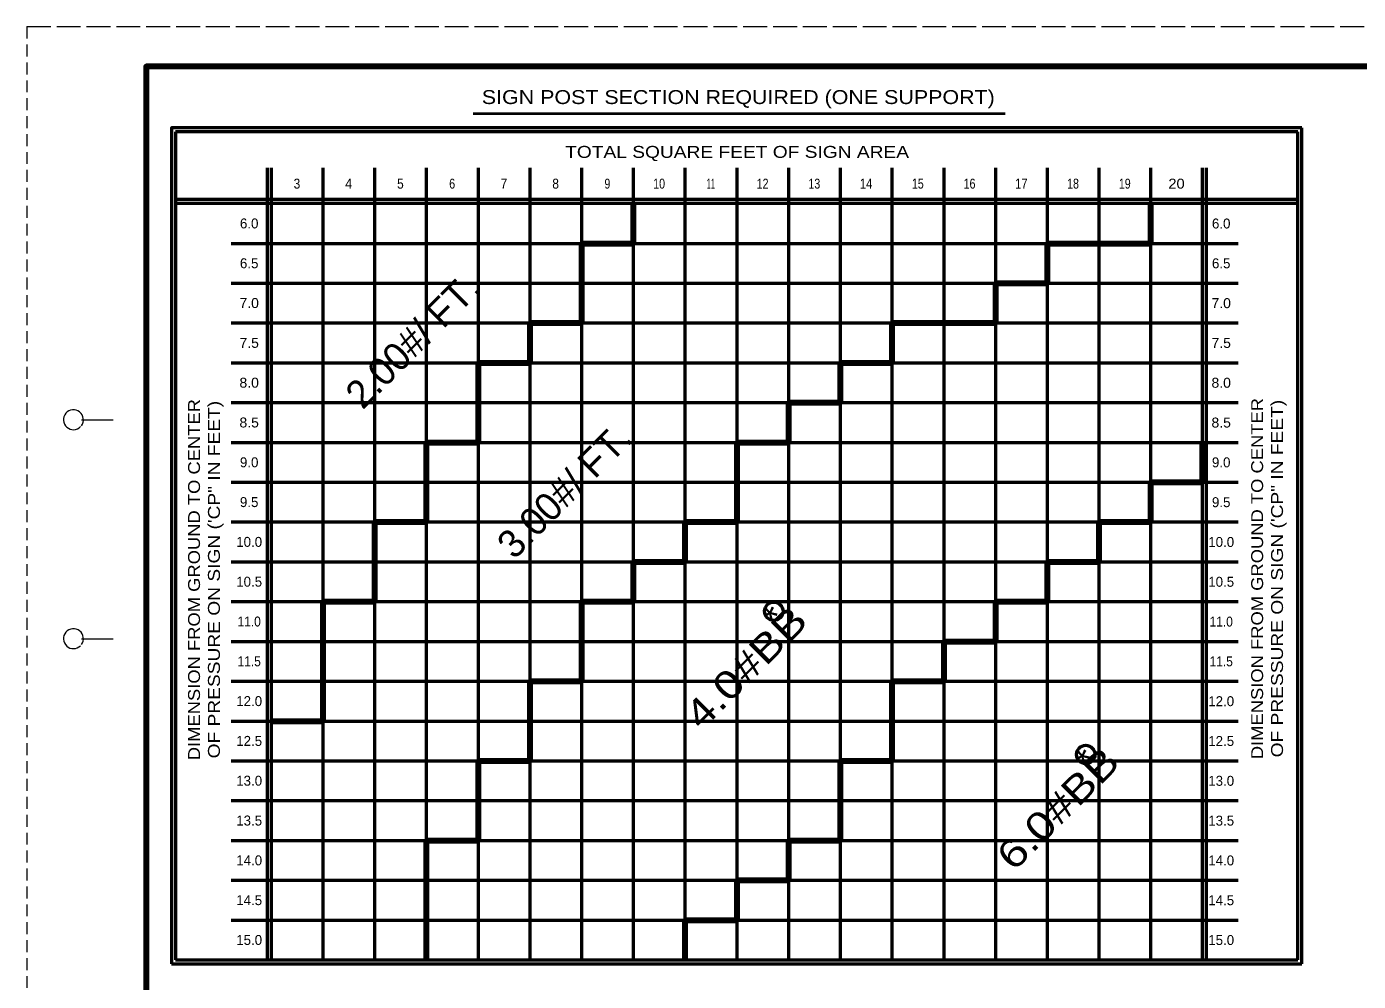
# Model space of a CAD drawing. Extents: x -2 to 678, y -1 to 439.
# Drawn here: x -1.8 to 332.9, y 199.5 to 439.3 of the extents above; entities that cross this region are included whole.
import ezdxf
from ezdxf.enums import TextEntityAlignment as Align

# ---------------------------------------------------------------- set-up
doc = ezdxf.new("R2010")
doc.units = 0
doc.linetypes.add('LONG_DASHED', pattern=[7.5, 6, -1.5])
doc.linetypes.add('MEDIUM_DASHED', pattern=[4.5, 3, -1.5])
doc.layers.add('1', color=7, linetype='Continuous', lineweight=53)
doc.layers.add('61', color=7, linetype='Continuous', lineweight=35)

msp = doc.modelspace()

# ---------------------------------------------------------------- linework, layer by layer
at = {"layer": '1', "linetype": 'MEDIUM_DASHED', "lineweight": 13}
msp.add_line((-1.693, 439.301), (-1.753, -0.739), dxfattribs=at)
at = {"layer": '1', "lineweight": 40}
msp.add_line((110.465, 417.498), (244.067, 417.498), dxfattribs=at)
at = {"layer": '1'}
for p, q in [((35.661, 412.86), (35.661, 204.86)), ((317.661, 412.86), (35.661, 412.86)), ((317.661, 204.86), (317.661, 412.86)), ((318.661, 203.86), (318.661, 413.86)), ((58.661, 403.86), (58.661, 204.86)), ((59.661, 403.86), (59.661, 204.86)), ((72.661, 403.86), (72.661, 395.86)), ((85.661, 403.86), (85.661, 314.86)), ((98.661, 403.86), (98.661, 334.86)), ((111.661, 403.86), (111.661, 354.86)), ((124.661, 403.86), (124.661, 364.86)), ((137.661, 403.86), (137.661, 384.86)), ((150.661, 403.86), (150.661, 394.86)), ((163.661, 403.86), (163.661, 314.86)), ((176.661, 403.86), (176.661, 334.86)), ((189.661, 403.86), (189.661, 344.86)), ((202.661, 403.86), (202.661, 354.86)), ((215.661, 403.86), (215.661, 364.86)), ((228.661, 403.86), (228.661, 284.86)), ((241.661, 403.86), (241.661, 374.86)), ((254.661, 403.86), (254.661, 384.86)), ((267.661, 403.86), (267.661, 314.86)), ((280.661, 403.86), (280.661, 394.86)), ((293.661, 334.86), (293.661, 403.86)), ((294.661, 204.86), (294.661, 403.86)), ((317.661, 395.86), (35.661, 395.86)), ((317.661, 394.86), (35.661, 394.86)), ((72.661, 395.86), (72.661, 294.86)), ((49.661, 384.86), (58.661, 384.86)), ((58.661, 384.86), (137.661, 384.86)), ((150.661, 384.86), (254.661, 384.86)), ((150.661, 384.86), (150.661, 304.86)), ((280.661, 384.86), (302.661, 384.86)), ((280.661, 384.86), (280.661, 324.86)), ((49.661, 374.86), (241.661, 374.86)), ((254.661, 374.86), (302.661, 374.86)), ((254.661, 374.86), (254.661, 304.86)), ((49.661, 364.86), (124.661, 364.86)), ((137.661, 364.86), (215.661, 364.86)), ((137.661, 364.86), (137.661, 294.86)), ((241.661, 364.86), (302.661, 364.86)), ((241.661, 364.86), (241.661, 294.86)), ((49.661, 354.86), (111.661, 354.86)), ((124.661, 354.86), (202.661, 354.86)), ((124.661, 354.86), (124.661, 274.86)), ((215.661, 354.86), (302.661, 354.86)), ((215.661, 354.86), (215.661, 274.86)), ((49.661, 344.86), (189.661, 344.86)), ((202.661, 344.86), (302.661, 344.86)), ((202.661, 344.86), (202.661, 254.86)), ((49.661, 334.86), (98.661, 334.86)), ((111.661, 334.86), (176.661, 334.86)), ((111.661, 334.86), (111.661, 254.86)), ((189.661, 334.86), (302.661, 334.86)), ((189.661, 334.86), (189.661, 234.86)), ((49.661, 324.86), (280.661, 324.86)), ((293.661, 204.86), (293.661, 324.86)), ((293.661, 324.86), (302.661, 324.86)), ((49.661, 314.86), (85.661, 314.86)), ((98.661, 314.86), (163.661, 314.86)), ((98.661, 314.86), (98.661, 234.86)), ((176.661, 314.86), (267.661, 314.86)), ((176.661, 314.86), (176.661, 224.86)), ((280.661, 314.86), (280.661, 204.86)), ((49.661, 304.86), (150.661, 304.86)), ((163.661, 304.86), (254.661, 304.86)), ((163.661, 304.86), (163.661, 214.86)), ((267.661, 304.86), (267.661, 204.86)), ((267.661, 304.86), (302.661, 304.86)), ((49.661, 294.86), (59.661, 294.86)), ((59.661, 294.86), (72.661, 294.86)), ((85.661, 294.86), (85.661, 204.86)), ((85.661, 294.86), (137.661, 294.86)), ((150.661, 294.86), (150.661, 204.86)), ((150.661, 294.86), (241.661, 294.86)), ((254.661, 294.86), (254.661, 204.86)), ((254.661, 294.86), (302.661, 294.86)), ((49.661, 284.86), (228.661, 284.86)), ((241.661, 284.86), (241.661, 204.86)), ((241.661, 284.86), (302.661, 284.86)), ((49.661, 274.86), (124.661, 274.86)), ((137.661, 274.86), (137.661, 204.86)), ((137.661, 274.86), (215.661, 274.86)), ((228.661, 274.86), (228.661, 204.86)), ((228.661, 274.86), (302.661, 274.86)), ((49.661, 264.86), (59.661, 264.86)), ((72.661, 264.86), (302.661, 264.86)), ((72.661, 264.86), (72.661, 204.86)), ((49.661, 254.86), (111.661, 254.86)), ((124.661, 254.86), (124.661, 204.86)), ((124.661, 254.86), (202.661, 254.86)), ((215.661, 254.86), (215.661, 204.86)), ((215.661, 254.86), (302.661, 254.86)), ((49.661, 244.86), (302.661, 244.86)), ((49.661, 234.86), (98.661, 234.86)), ((111.661, 234.86), (111.661, 204.86)), ((111.661, 234.86), (189.661, 234.86)), ((202.661, 234.86), (202.661, 204.86)), ((202.661, 234.86), (302.661, 234.86)), ((49.661, 224.86), (176.661, 224.86)), ((189.661, 224.86), (189.661, 204.86)), ((189.661, 224.86), (302.661, 224.86)), ((49.661, 214.86), (163.661, 214.86)), ((176.661, 214.86), (176.661, 204.86)), ((176.661, 214.86), (302.661, 214.86)), ((35.661, 204.86), (317.661, 204.86)), ((34.661, 203.86), (318.661, 203.86))]:
    msp.add_line(p, q, dxfattribs=at)
at = {"layer": '1', "lineweight": 200}
for p, q in [((150.661, 394.86), (150.661, 384.86)), ((280.661, 394.86), (280.661, 384.86)), ((137.661, 384.86), (137.661, 364.86)), ((137.661, 384.86), (150.661, 384.86)), ((254.661, 384.86), (280.661, 384.86)), ((254.661, 384.86), (254.661, 374.86)), ((241.661, 374.86), (254.661, 374.86)), ((241.661, 374.86), (241.661, 364.86)), ((124.661, 364.86), (124.661, 354.86)), ((124.661, 364.86), (137.661, 364.86)), ((215.661, 364.86), (241.661, 364.86)), ((215.661, 364.86), (215.661, 354.86)), ((111.661, 354.86), (111.661, 334.86)), ((111.661, 354.86), (124.661, 354.86)), ((202.661, 354.86), (215.661, 354.86)), ((202.661, 354.86), (202.661, 344.86)), ((189.661, 344.86), (202.661, 344.86)), ((189.661, 344.86), (189.661, 334.86)), ((98.661, 334.86), (98.661, 314.86)), ((98.661, 334.86), (111.661, 334.86)), ((176.661, 334.86), (189.661, 334.86)), ((176.661, 334.86), (176.661, 314.86)), ((293.661, 324.86), (293.661, 334.86)), ((280.661, 324.86), (293.661, 324.86)), ((280.661, 324.86), (280.661, 314.86)), ((85.661, 314.86), (98.661, 314.86)), ((85.661, 314.86), (85.661, 294.86)), ((163.661, 314.86), (176.661, 314.86)), ((163.661, 314.86), (163.661, 304.86)), ((267.661, 314.86), (280.661, 314.86)), ((267.661, 314.86), (267.661, 304.86)), ((150.661, 304.86), (163.661, 304.86)), ((150.661, 304.86), (150.661, 294.86)), ((254.661, 304.86), (267.661, 304.86)), ((254.661, 304.86), (254.661, 294.86)), ((72.661, 294.86), (72.661, 264.86)), ((72.661, 294.86), (85.661, 294.86)), ((137.661, 294.86), (150.661, 294.86)), ((137.661, 294.86), (137.661, 274.86)), ((241.661, 294.86), (254.661, 294.86)), ((241.661, 294.86), (241.661, 284.86)), ((228.661, 284.86), (241.661, 284.86)), ((228.661, 284.86), (228.661, 274.86)), ((124.661, 274.86), (137.661, 274.86)), ((124.661, 274.86), (124.661, 254.86)), ((215.661, 274.86), (228.661, 274.86)), ((215.661, 274.86), (215.661, 254.86)), ((59.661, 264.86), (72.661, 264.86)), ((111.661, 254.86), (124.661, 254.86)), ((111.661, 254.86), (111.661, 234.86)), ((202.661, 254.86), (215.661, 254.86)), ((202.661, 254.86), (202.661, 234.86)), ((98.661, 234.86), (111.661, 234.86)), ((98.661, 234.86), (98.661, 204.86)), ((189.661, 234.86), (202.661, 234.86)), ((189.661, 234.86), (189.661, 224.86)), ((176.661, 224.86), (189.661, 224.86)), ((176.661, 224.86), (176.661, 214.86)), ((163.661, 214.86), (163.661, 204.86)), ((163.661, 214.86), (176.661, 214.86))]:
    msp.add_line(p, q, dxfattribs=at)
at = {"layer": '1'}
for points in [[(318.661, 413.86), (34.661, 413.86), (34.661, 203.86)], [(280.661, 314.86), (294.661, 314.86), (302.661, 314.86)]]:
    msp.add_lwpolyline(points, dxfattribs=at)
for centre in [(185.98, 292.447), (264.365, 256.449)]:
    msp.add_circle(centre, 2.31, dxfattribs=at)
at = {"layer": '61', "linetype": 'LONG_DASHED', "lineweight": 13}
msp.add_line((-1.693, 439.301), (678.327, 439.301), dxfattribs=at)
at = {"layer": '61', "lineweight": 13}
for p, q in [((12.027, 340.541), (20.007, 340.561)), ((12.007, 285.541), (20.007, 285.541))]:
    msp.add_line(p, q, dxfattribs=at)
at = {"layer": '61', "lineweight": 158}
msp.add_lwpolyline([(667.347, 429.301), (28.307, 429.301), (28.307, 9.281)], dxfattribs=at)
at = {"layer": '61', "lineweight": 13}
for centre, end in [((10.004, 340.543), 316.23216), ((10.004, 285.543), 315.37577)]:
    msp.add_arc(centre, 2.5, 323.13009, end, dxfattribs=at)

# ---------------------------------------------------------------- texts
at = {"layer": '1'}
for s, height, width, p in [('SIGN POST SECTION REQUIRED (ONE SUPPORT)', 3.5, 1.15, (177.055, 419.856)), ('TOTAL SQUARE FEET OF SIGN AREA', 3, 1.2, (176.754, 406.333)), ('3', 2.5, 0.9, (66.161, 398.61)), ('4', 2.5, 0.95, (79.161, 398.61)), ('5', 2.5, 0.9, (92.161, 398.61)), ('6', 2.5, 0.8, (105.161, 398.61)), ('7', 2.5, 0.9, (118.161, 398.61)), ('8', 2.5, 0.9, (131.161, 398.61)), ('9', 2.5, 0.8, (144.161, 398.61)), ('10', 2.5, 0.8, (157.161, 398.61)), ('11', 2.5, 0.55, (170.161, 398.61)), ('12', 2.5, 0.8, (183.161, 398.61)), ('13', 2.5, 0.8, (196.161, 398.61)), ('14', 2.5, 0.85, (209.161, 398.61)), ('15', 2.5, 0.8, (222.161, 398.61)), ('16', 2.5, 0.8, (235.161, 398.61)), ('17', 2.5, 0.85, (248.161, 398.61)), ('18', 2.5, 0.8, (261.161, 398.61)), ('19', 2.5, 0.8, (274.161, 398.61)), ('20', 2.5, 1.1, (287.161, 398.61)), ('7.0', 2.5, 1.05, (54.161, 368.61)), ('7.0', 2.5, 1.05, (298.388, 368.59)), ('7.5', 2.5, 1.05, (54.161, 358.61)), ('7.5', 2.5, 1.05, (298.388, 358.59)), ('8.0', 2.5, 1.05, (54.161, 348.61)), ('8.0', 2.5, 1.05, (298.388, 348.59)), ('8.5', 2.5, 1.05, (54.161, 338.61)), ('8.5', 2.5, 1.05, (298.388, 338.59)), ('11.0', 2.5, 0.9, (54.161, 288.61)), ('11.0', 2.5, 0.9, (298.388, 288.59)), ('11.5', 2.5, 0.9, (54.161, 278.61)), ('11.5', 2.5, 0.9, (298.388, 278.59))]:
    msp.add_text(s, height=height, dxfattribs=dict(at, width=width)).set_placement(p, align=Align.CENTER)
for s, p in [('6.0', (54.161, 388.61)), ('6.0', (298.387, 388.59)), ('6.5', (54.161, 378.61)), ('6.5', (298.387, 378.59)), ('9.0', (54.161, 328.61)), ('9.0', (298.387, 328.59)), ('9.5', (54.161, 318.61)), ('9.5', (298.387, 318.59)), ('10.0', (54.161, 308.61)), ('10.0', (298.388, 308.59)), ('10.5', (54.161, 298.61)), ('10.5', (298.388, 298.59)), ('12.0', (54.161, 268.61)), ('12.0', (298.388, 268.59)), ('12.5', (54.161, 258.61)), ('12.5', (298.388, 258.59)), ('13.0', (54.161, 248.61)), ('13.0', (298.388, 248.59)), ('13.5', (54.161, 238.61)), ('13.5', (298.388, 238.59)), ('14.0', (54.161, 228.61)), ('14.0', (298.387, 228.59)), ('14.5', (54.161, 218.61)), ('14.5', (298.387, 218.59)), ('15.0', (54.161, 208.61)), ('15.0', (298.388, 208.59))]:
    msp.add_text(s, height=2.5, dxfattribs=at).set_placement(p, align=Align.CENTER)
for s, p in [('2.00#/ FT.', (97.746, 357.978)), ('3.00#/ FT.', (135.836, 320.28)), ('*', (188.685, 288.33)), ('*', (267.161, 252.414))]:
    msp.add_text(s, height=7, rotation=45, dxfattribs=at).set_placement(p, align=Align.CENTER)
for s, height, rotation, width, p in [('DIMENSION FROM GROUND TO CENTER', 3, 90, 1.15, (41.809, 300.382)), ('OF PRESSURE ON SIGN (\'CP" IN FEET)', 3, 90, 1.2, (46.809, 300.382)), ('DIMENSION FROM GROUND TO CENTER', 3, 90, 1.15, (308.919, 300.642)), ('OF PRESSURE ON SIGN (\'CP" IN FEET)', 3, 90, 1.2, (313.919, 300.642)), ('4.0#BB', 7, 45, 1.25, (181.424, 275.894)), ('6.0#BB', 7, 45, 1.25, (259.833, 240.426))]:
    msp.add_text(s, height=height, rotation=rotation, dxfattribs=dict(at, width=width)).set_placement(p, align=Align.CENTER)

doc.saveas('drawing.dxf')
